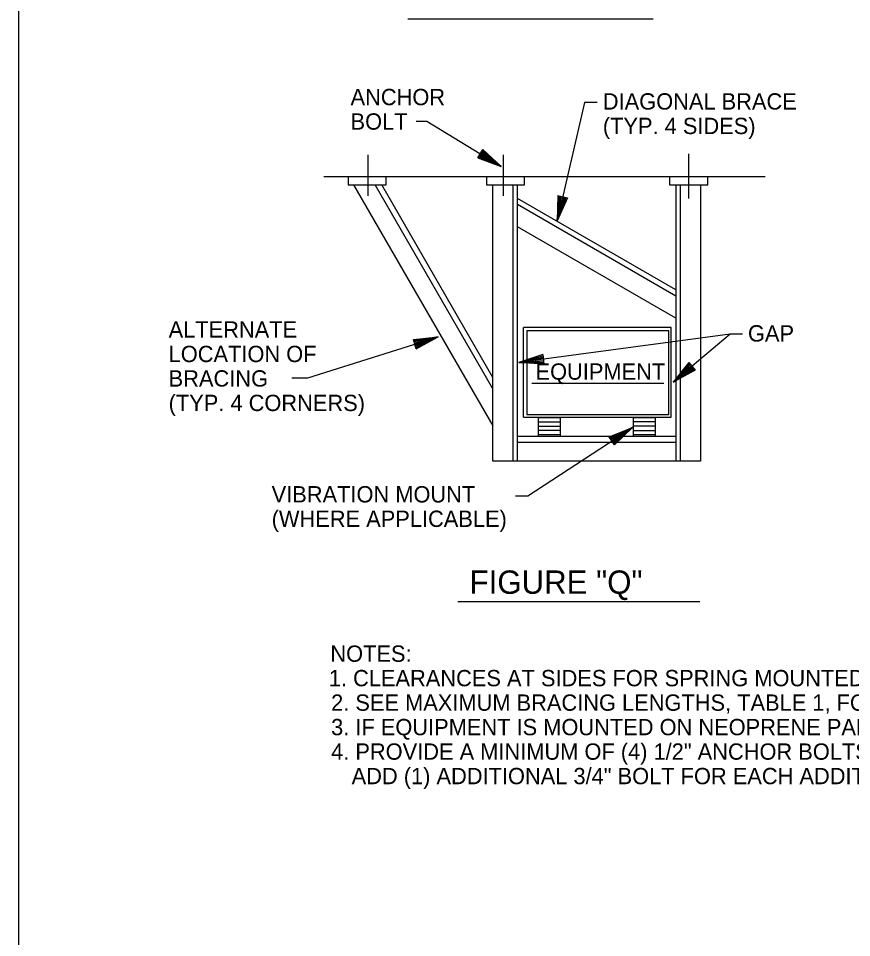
# Model space of a CAD drawing. Extents: x 9999.96 to 10005.26, y 9999.88 to 10002.38.
# Drawn here: x 10001.648 to 10002.159, y 10001.252 to 10001.815 of the extents above; entities that cross this region are included whole.
import ezdxf

# ---------------------------------------------------------------- set-up
doc = ezdxf.new("R2010")
doc.units = 0
doc.layers.add('Level 2', color=7, linetype='Continuous')

msp = doc.modelspace()

# ---------------------------------------------------------------- linework, layer by layer
at = {"layer": 'Level 2'}
for p, q in [((10001.64817, 10002.34286), (10001.64817, 9999.9262)), ((10001.88692, 10001.8151), (10002.03735, 10001.8151)), ((10001.92973, 10001.72975), (10001.93286, 10001.7349)), ((10001.94416, 10001.7245), (10001.93204, 10001.73358)), ((10001.94416, 10001.7245), (10001.93243, 10001.7342)), ((10001.93286, 10001.7349), (10001.94416, 10001.7245)), ((10001.86257, 10001.70654), (10001.86257, 10001.73164)), ((10001.92973, 10001.72975), (10001.94416, 10001.7245)), ((10001.94416, 10001.7245), (10001.93013, 10001.73041)), ((10001.94416, 10001.7245), (10001.93054, 10001.73114)), ((10001.94416, 10001.7245), (10001.93091, 10001.7317)), ((10001.93127, 10001.7323), (10001.94416, 10001.7245)), ((10001.94416, 10001.7245), (10001.93167, 10001.73294)), ((10001.94544, 10001.70654), (10001.94544, 10001.73164)), ((10002.05905, 10001.70492), (10002.05905, 10001.73234)), ((10001.83539, 10001.71833), (10002.10588, 10001.71833)), ((10001.93911, 10001.56568), (10001.85389, 10001.7133)), ((10001.93904, 10001.58838), (10001.86692, 10001.7133)), ((10001.93904, 10001.59527), (10001.8709, 10001.7133)), ((10001.93904, 10001.54401), (10001.93904, 10001.7133)), ((10001.9513, 10001.7133), (10001.9513, 10001.54401)), ((10001.95415, 10001.54401), (10001.95415, 10001.7133)), ((10002.05114, 10001.7133), (10002.05114, 10001.54401)), ((10002.05397, 10001.54401), (10002.05397, 10001.7133)), ((10002.06624, 10001.7133), (10002.06624, 10001.54401)), ((10001.9789, 10001.70668), (10001.97841, 10001.69133)), ((10001.97841, 10001.69133), (10001.97965, 10001.7065)), ((10001.97841, 10001.69133), (10001.98047, 10001.70633)), ((10001.97841, 10001.69133), (10001.98111, 10001.70616)), ((10001.9818, 10001.70601), (10001.97841, 10001.69133)), ((10001.97841, 10001.69133), (10001.98254, 10001.70583)), ((10001.97841, 10001.69133), (10001.98327, 10001.70567)), ((10001.97841, 10001.69133), (10001.98397, 10001.7055)), ((10001.98477, 10001.7053), (10001.97841, 10001.69133)), ((10001.9789, 10001.70668), (10001.98477, 10001.7053)), ((10002.05114, 10001.649), (10001.95415, 10001.705)), ((10002.05114, 10001.64516), (10001.95415, 10001.70116)), ((10002.05114, 10001.63156), (10001.95415, 10001.68756)), ((10002.0484, 10001.62591), (10001.9578, 10001.62591)), ((10001.9578, 10001.571), (10001.9578, 10001.62591)), ((10002.0484, 10001.571), (10002.0484, 10001.62591)), ((10001.89029, 10001.61851), (10001.90555, 10001.62011)), ((10001.89208, 10001.61275), (10001.89029, 10001.61851)), ((10001.90555, 10001.62011), (10001.89052, 10001.61772)), ((10001.90555, 10001.62011), (10001.89073, 10001.61703)), ((10001.90555, 10001.62011), (10001.89097, 10001.61632)), ((10001.89118, 10001.61559), (10001.90555, 10001.62011)), ((10001.90555, 10001.62011), (10001.8914, 10001.61493)), ((10001.90555, 10001.62011), (10001.89158, 10001.61428)), ((10001.90555, 10001.62011), (10001.89185, 10001.61349)), ((10001.89208, 10001.61275), (10001.90555, 10001.62011)), ((10001.96954, 10001.60932), (10001.95502, 10001.60434)), ((10001.95502, 10001.60434), (10001.96965, 10001.60856)), ((10001.95502, 10001.60434), (10001.96978, 10001.60773)), ((10001.95502, 10001.60434), (10001.96984, 10001.60706)), ((10001.96995, 10001.60638), (10001.95502, 10001.60434)), ((10001.95502, 10001.60434), (10001.97004, 10001.60563)), ((10001.95502, 10001.60434), (10001.97015, 10001.60489)), ((10001.97033, 10001.60335), (10001.95502, 10001.60434)), ((10001.95502, 10001.60434), (10001.97024, 10001.60417)), ((10001.96954, 10001.60932), (10001.97033, 10001.60335)), ((10002.0592, 10001.60439), (10002.04963, 10001.59239)), ((10002.0592, 10001.60439), (10002.06307, 10001.59977)), ((10002.04963, 10001.59239), (10002.05969, 10001.6038)), ((10002.04963, 10001.59239), (10002.06025, 10001.60317)), ((10002.04963, 10001.59239), (10002.06067, 10001.60265)), ((10002.06113, 10001.60211), (10002.04963, 10001.59239)), ((10002.04963, 10001.59239), (10002.0616, 10001.60153)), ((10002.04963, 10001.59239), (10002.06209, 10001.60097)), ((10002.04963, 10001.59239), (10002.06255, 10001.60041)), ((10002.06307, 10001.59977), (10002.04963, 10001.59239)), ((10001.96289, 10001.59174), (10002.0439, 10001.59174)), ((10001.9578, 10001.571), (10002.0484, 10001.571)), ((10001.98022, 10001.57047), (10001.96688, 10001.57047)), ((10001.96689, 10001.55915), (10001.96689, 10001.57102)), ((10001.98022, 10001.57102), (10001.98022, 10001.55925)), ((10002.02516, 10001.55915), (10002.02516, 10001.57102)), ((10002.03849, 10001.57056), (10002.02516, 10001.57056)), ((10002.03849, 10001.57102), (10002.03849, 10001.55925)), ((10001.98022, 10001.56791), (10001.96689, 10001.56791)), ((10001.98021, 10001.56531), (10001.96689, 10001.56531)), ((10002.01036, 10001.55897), (10002.02461, 10001.56466)), ((10002.02461, 10001.56466), (10002.0108, 10001.55827)), ((10002.02461, 10001.56466), (10002.01119, 10001.55767)), ((10002.02461, 10001.56466), (10002.0116, 10001.55704)), ((10002.01201, 10001.55641), (10002.02461, 10001.56466)), ((10002.02461, 10001.56466), (10002.01241, 10001.55582)), ((10002.02461, 10001.56466), (10002.01275, 10001.55525)), ((10002.02461, 10001.56466), (10002.01323, 10001.55455)), ((10002.01365, 10001.55392), (10002.02461, 10001.56466)), ((10002.03848, 10001.5654), (10002.02515, 10001.5654)), ((10002.03849, 10001.568), (10002.02516, 10001.568)), ((10002.05114, 10001.5591), (10001.95415, 10001.5591)), ((10001.98022, 10001.56275), (10001.96689, 10001.56275)), ((10001.98022, 10001.56019), (10001.96689, 10001.56019)), ((10002.01365, 10001.55392), (10002.01036, 10001.55897)), ((10002.02515, 10001.56024), (10002.03848, 10001.56024)), ((10002.02516, 10001.56284), (10002.03849, 10001.56284)), ((10002.05114, 10001.5554), (10001.95415, 10001.5554)), ((10002.06624, 10001.54401), (10001.93904, 10001.54401)), ((10001.91751, 10001.45798), (10002.06594, 10001.45798))]:
    msp.add_line(p, q, dxfattribs=at)
for points in [[(10002.00288, 10001.76365), (10001.99526, 10001.76365), (10001.97841, 10001.69133)], [(10001.89196, 10001.75223), (10001.89848, 10001.75223), (10001.94416, 10001.7245)], [(10001.85028, 10001.71833), (10001.85028, 10001.7133), (10001.87361, 10001.7133), (10001.87361, 10001.71833)], [(10001.93509, 10001.71833), (10001.93509, 10001.7133), (10001.95843, 10001.7133), (10001.95843, 10001.71833)], [(10002.04736, 10001.71833), (10002.04736, 10001.7133), (10002.0707, 10001.7133), (10002.0707, 10001.71833)], [(10002.08443, 10001.62174), (10001.95502, 10001.60434)], [(10002.09203, 10001.62174), (10002.08443, 10001.62174), (10002.04963, 10001.59239)], [(10001.81584, 10001.5951), (10001.82563, 10001.5951), (10001.90555, 10001.62011)], [(10001.95285, 10001.52279), (10001.96046, 10001.52279), (10002.02461, 10001.56466)]]:
    msp.add_lwpolyline(points, dxfattribs=at)
msp.add_lwpolyline([(10001.95984, 10001.57251), (10002.04688, 10001.57251), (10002.04688, 10001.62382), (10001.95984, 10001.62382)], close=True, dxfattribs=at)

# ---------------------------------------------------------------- texts
for s, height, p in [('ANCHOR', 0.01, (10001.85178, 10001.7621)), ('DIAGONAL BRACE', 0.01, (10002.00642, 10001.7594)), ('BOLT', 0.01, (10001.85178, 10001.7471)), ('(TYP. 4 SIDES)', 0.01, (10002.00642, 10001.7444)), ('ALTERNATE', 0.01, (10001.74027, 10001.61967)), ('GAP', 0.01, (10002.09538, 10001.61728)), ('LOCATION OF', 0.01, (10001.74027, 10001.60467)), ('EQUIPMENT', 0.01, (10001.96517, 10001.59389)), ('BRACING', 0.01, (10001.74027, 10001.58967)), ('(TYP. 4 CORNERS)', 0.01, (10001.74027, 10001.57467)), ('VIBRATION MOUNT', 0.01, (10001.80341, 10001.51868)), ('(WHERE APPLICABLE)', 0.01, (10001.80341, 10001.50368)), ('FIGURE "Q"', 0.014301, (10001.92474, 10001.46271)), ('NOTES:', 0.01, (10001.8394, 10001.42105)), ('1. CLEARANCES AT SIDES FOR SPRING MOUNTED EQUIPMENT AS IN FIG. "R" & "S", SHALL BE IN ACCORDANCE WITH MFR\'S. RECOMMENDATIONS.', 0.01, (10001.83844, 10001.40605)), ('2. SEE MAXIMUM BRACING LENGTHS, TABLE 1, FOR BRACE SIZES.', 0.01, (10001.83986, 10001.39105)), ('3. IF EQUIPMENT IS MOUNTED ON NEOPRENE PADS, ANCHOR BOLTS SHALL BE ISOLATED FROM EQUIPMENT BY A NEOPRENE SLEEVE AND WASHER.', 0.01, (10001.83986, 10001.37605)), ('4. PROVIDE A MINIMUM OF (4) 1/2" ANCHOR BOLTS FOR EQUIPMENT UP TO 10,000 LBS. AND (4) 3/4" BOLTS FOR EQUIPMENT 10,000 LBS. OR GREATER.', 0.01, (10001.83986, 10001.36105)), ('   ADD (1) ADDITIONAL 3/4" BOLT FOR EACH ADDITIONAL 2,500 LBS.', 0.01, (10001.8413, 10001.34605))]:
    msp.add_text(s, height=height, dxfattribs=at).set_placement(p)

doc.saveas('drawing.dxf')
